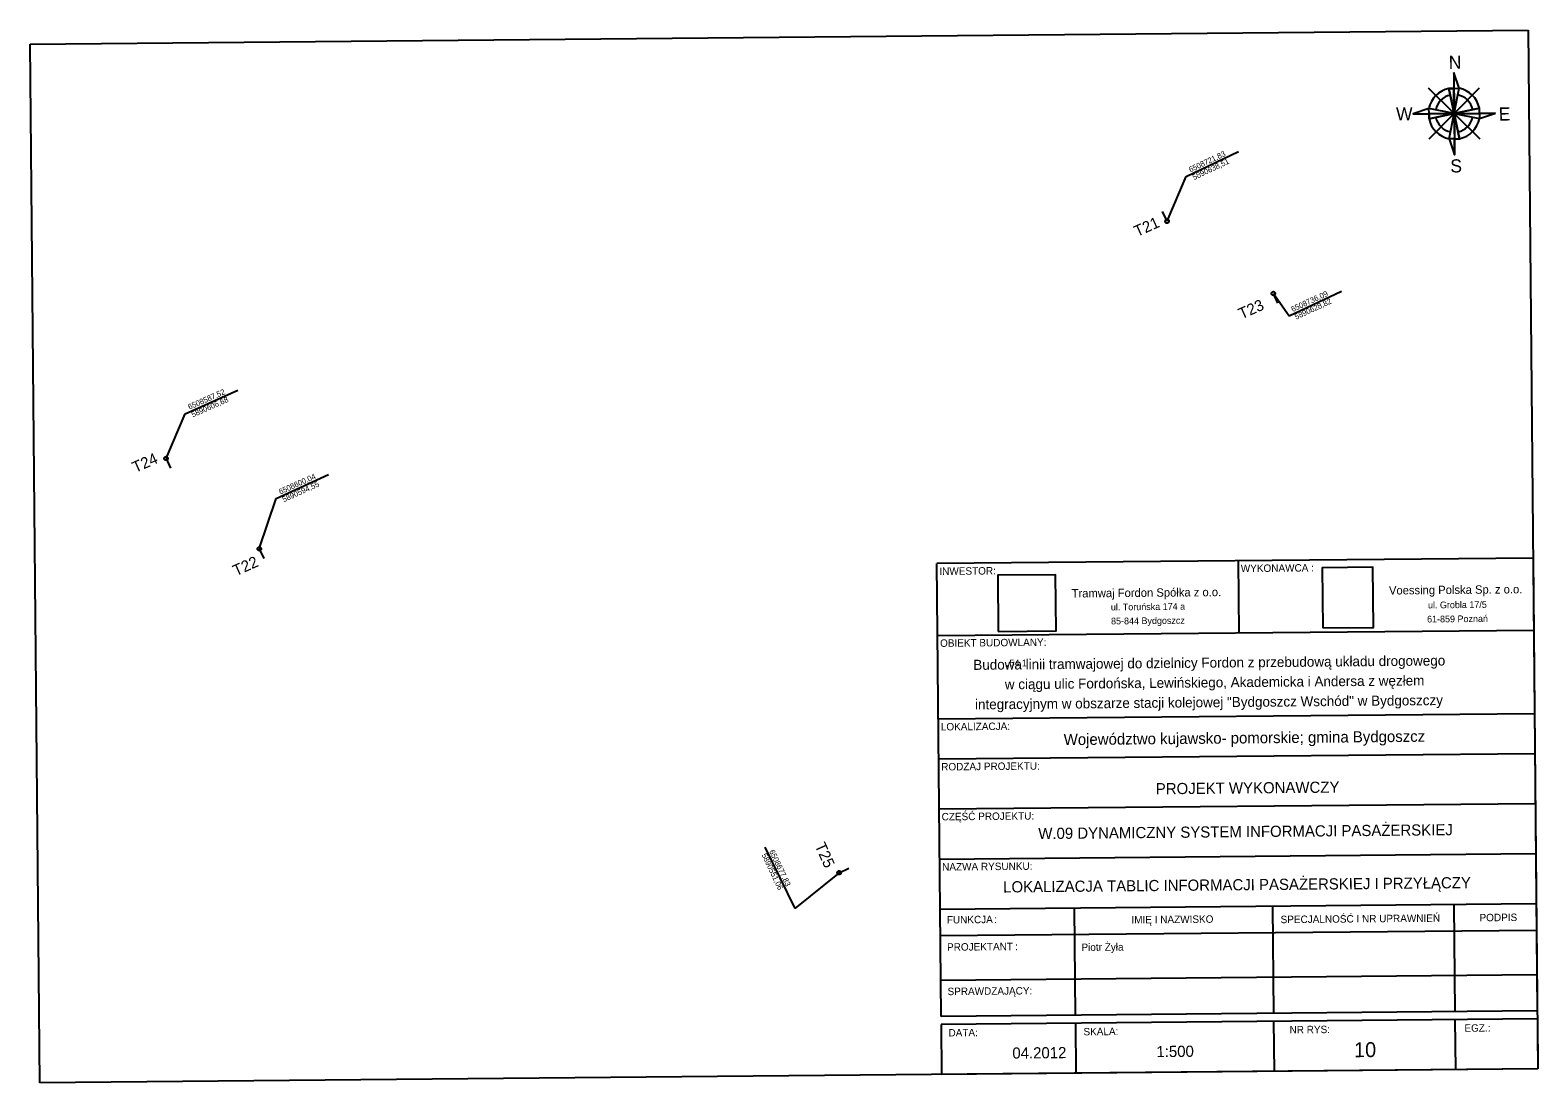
# Model space of a CAD drawing. Extents: x 6505045 to 6511721, y 5887996 to 5893535.
# Drawn here: x 6508569.3 to 6508771.6, y 5890522.8 to 5890664.2 of the extents above; entities that cross this region are included whole.
import ezdxf

# ---------------------------------------------------------------- set-up
doc = ezdxf.new("R2010")
doc.units = 0
for name, color, linetype in [('__legenda', 7, 'Continuous'), ('Default', 7, 'Continuous'), ('P_1 tablica LCD', 7, 'Continuous'), ('P_2 tablice LCD', 7, 'Continuous'), ('P_lokalizacja slupka', 7, 'Continuous'), ('P_opisy', 7, 'Continuous'), ('P_tabela', 7, 'Continuous'), ('P_wsporzedne', 7, 'Continuous'), ('P_znak północy', 7, 'Continuous'), ('SA_Linie-020', 7, 'Continuous'), ('SA_Stempel_Text-020', 7, 'Continuous'), ('SA_Stempel_Text-030', 7, 'Continuous'), ('SA_Stempel_Text-035', 7, 'Continuous'), ('SA_Unterschrift_Text', 7, 'Continuous'), ('WWRPP_801', 7, 'Continuous')]:
    doc.layers.add(name, color=color, linetype=linetype)

msp = doc.modelspace()

# ---------------------------------------------------------------- linework, layer by layer
at = {"layer": '__legenda'}
msp.add_lwpolyline([(6508742.72, 5890583.93), (6508749.52, 5890583.99), (6508749.45, 5890592.06), (6508742.65, 5890592)], close=True, dxfattribs=at)
at = {"layer": 'Default'}
msp.add_lwpolyline([(6508699.19, 5890583.46), (6508706.93, 5890583.53), (6508706.86, 5890591.07), (6508699.12, 5890590.99)], close=True, dxfattribs=at)
at = {"layer": 'P_1 tablica LCD'}
for p, q in [((6508736.7, 5890627.5), (6508736.09, 5890628.82)), ((6508587.52, 5890606.68), (6508588.12, 5890605.36))]:
    msp.add_line(p, q, dxfattribs=at)
at = {"layer": 'P_2 tablice LCD'}
for p, q in [((6508721.83, 5890638.51), (6508721.23, 5890639.83)), ((6508600.04, 5890594.55), (6508600.65, 5890593.24)), ((6508677.83, 5890551.06), (6508679.15, 5890551.67))]:
    msp.add_line(p, q, dxfattribs=at)
at = {"layer": 'P_lokalizacja slupka'}
for centre in [(6508721.83, 5890638.51), (6508736.09, 5890628.82), (6508736.09, 5890628.82), (6508587.52, 5890606.68), (6508600.04, 5890594.55), (6508677.83, 5890551.06)]:
    msp.add_circle(centre, 0.25, dxfattribs=at)
at = {"layer": 'P_tabela'}
for p, q in [((6508569.29, 5890662.3), (6508770.28, 5890664.17)), ((6508569.29, 5890662.3), (6508770.28, 5890664.17)), ((6508770.28, 5890664.17), (6508771.58, 5890524.72)), ((6508770.28, 5890664.17), (6508771.58, 5890524.72)), ((6508570.59, 5890522.85), (6508569.29, 5890662.3)), ((6508570.59, 5890522.85), (6508569.29, 5890662.3)), ((6508771.58, 5890524.72), (6508570.59, 5890522.85)), ((6508771.58, 5890524.72), (6508570.59, 5890522.85))]:
    msp.add_line(p, q, dxfattribs=at)
at = {"layer": 'P_wsporzedne'}
for p, q in [((6508724.4, 5890644.51), (6508731.4, 5890647.89)), ((6508721.83, 5890638.51), (6508724.4, 5890644.51)), ((6508736.09, 5890628.82), (6508738.2, 5890625.83)), ((6508738.2, 5890625.83), (6508745.24, 5890629.13)), ((6508590.08, 5890612.67), (6508597.17, 5890615.85)), ((6508587.52, 5890606.68), (6508590.08, 5890612.67)), ((6508602.28, 5890601.28), (6508609.34, 5890604.52)), ((6508600.04, 5890594.55), (6508602.28, 5890601.28)), ((6508667.88, 5890554.5), (6508671.87, 5890546.25)), ((6508677.83, 5890551.06), (6508671.87, 5890546.25))]:
    msp.add_line(p, q, dxfattribs=at)
at = {"layer": 'P_znak północy'}
for p, q in [((6508760.3, 5890658.49), (6508760.41, 5890647.45)), ((6508760.3, 5890658.49), (6508760.41, 5890647.45)), ((6508760.34, 5890652.97), (6508756.91, 5890656.36)), ((6508760.34, 5890652.97), (6508756.91, 5890656.36)), ((6508759.63, 5890656.35), (6508760.32, 5890656.35)), ((6508760.35, 5890652.98), (6508759.63, 5890656.35)), ((6508759.63, 5890656.35), (6508760.32, 5890656.35)), ((6508760.35, 5890652.98), (6508759.63, 5890656.35)), ((6508760.32, 5890656.35), (6508761.01, 5890656.36)), ((6508760.32, 5890656.35), (6508761.01, 5890656.36)), ((6508760.35, 5890652.98), (6508761.01, 5890656.36)), ((6508760.35, 5890652.98), (6508761.01, 5890656.36)), ((6508760.36, 5890652.99), (6508763.74, 5890656.42)), ((6508760.36, 5890652.99), (6508763.74, 5890656.42)), ((6508754.84, 5890652.92), (6508765.88, 5890653.02)), ((6508754.84, 5890652.92), (6508765.88, 5890653.02)), ((6508760.35, 5890652.98), (6508756.97, 5890653.63)), ((6508760.35, 5890652.98), (6508756.97, 5890653.63)), ((6508760.36, 5890652.99), (6508756.97, 5890649.53)), ((6508760.36, 5890652.99), (6508756.97, 5890649.53)), ((6508756.98, 5890652.25), (6508760.35, 5890652.98)), ((6508756.98, 5890652.25), (6508760.35, 5890652.98)), ((6508756.98, 5890652.94), (6508760.34, 5890652.97)), ((6508760.34, 5890652.97), (6508756.98, 5890652.25)), ((6508756.98, 5890652.94), (6508760.34, 5890652.97)), ((6508760.34, 5890652.97), (6508756.98, 5890652.25)), ((6508756.98, 5890652.25), (6508756.98, 5890652.94)), ((6508756.98, 5890652.25), (6508756.98, 5890652.94)), ((6508759.7, 5890649.59), (6508760.35, 5890652.98)), ((6508759.7, 5890649.59), (6508760.35, 5890652.98)), ((6508760.35, 5890652.98), (6508763.73, 5890653.7)), ((6508760.35, 5890652.98), (6508763.73, 5890653.7)), ((6508760.35, 5890652.98), (6508763.74, 5890652.31)), ((6508760.35, 5890652.98), (6508761.08, 5890649.6)), ((6508760.35, 5890652.98), (6508763.74, 5890652.31)), ((6508760.35, 5890652.98), (6508761.08, 5890649.6)), ((6508760.36, 5890652.99), (6508763.8, 5890649.59)), ((6508760.36, 5890652.99), (6508763.8, 5890649.59))]:
    msp.add_line(p, q, dxfattribs=at)
for points in [[(6508760.3, 5890658.49), (6508760.32, 5890656.35), (6508760.32, 5890656.35), (6508761.01, 5890656.36), (6508760.3, 5890658.49)], [(6508760.3, 5890658.49), (6508760.32, 5890656.35), (6508760.32, 5890656.35), (6508761.01, 5890656.36), (6508760.3, 5890658.49)], [(6508760.36, 5890652.99), (6508760.32, 5890656.35), (6508759.63, 5890656.34), (6508760.35, 5890652.98), (6508760.36, 5890652.99)], [(6508760.36, 5890652.99), (6508760.32, 5890656.35), (6508759.63, 5890656.34), (6508760.35, 5890652.98), (6508760.36, 5890652.99)], [(6508756.98, 5890652.94), (6508756.97, 5890653.63), (6508754.84, 5890652.92), (6508756.98, 5890652.94)], [(6508756.98, 5890652.94), (6508756.97, 5890653.63), (6508754.84, 5890652.92), (6508756.98, 5890652.94)], [(6508760.34, 5890652.97), (6508756.98, 5890652.94), (6508756.98, 5890652.25), (6508760.34, 5890652.97)], [(6508760.34, 5890652.97), (6508756.98, 5890652.94), (6508756.98, 5890652.25), (6508760.34, 5890652.97)], [(6508760.36, 5890652.98), (6508760.36, 5890652.98), (6508760.37, 5890652.97), (6508763.73, 5890653), (6508763.73, 5890653.7), (6508760.36, 5890652.98)], [(6508760.36, 5890652.98), (6508760.36, 5890652.98), (6508760.37, 5890652.97), (6508763.73, 5890653), (6508763.73, 5890653.7), (6508760.36, 5890652.98)], [(6508760.39, 5890649.59), (6508761.08, 5890649.6), (6508760.36, 5890652.96), (6508760.39, 5890649.59)], [(6508760.39, 5890649.59), (6508761.08, 5890649.6), (6508760.36, 5890652.96), (6508760.39, 5890649.59)], [(6508765.88, 5890653.02), (6508763.73, 5890653), (6508763.74, 5890652.31), (6508765.88, 5890653.02)], [(6508765.88, 5890653.02), (6508763.73, 5890653), (6508763.74, 5890652.31), (6508765.88, 5890653.02)], [(6508760.39, 5890649.59), (6508759.7, 5890649.59), (6508760.41, 5890647.45), (6508760.39, 5890649.59)], [(6508760.39, 5890649.59), (6508759.7, 5890649.59), (6508760.41, 5890647.45), (6508760.39, 5890649.59)]]:
    msp.add_lwpolyline(points, dxfattribs=at)
for centre, radius, start, end in [((6508760.35, 5890652.98), 3.45, 102.0474, 168.9738), ((6508760.35, 5890652.98), 3.45, 102.0474, 168.9738), ((6508760.36, 5890652.99), 2.53, 102.1671, 169.2958), ((6508760.36, 5890652.99), 2.53, 102.1671, 169.2958), ((6508760.36, 5890652.99), 2.53, 11.7816, 78.9353), ((6508760.36, 5890652.99), 2.53, 11.7816, 78.9353), ((6508760.36, 5890652.98), 3.45, 12.0554, 79.0163), ((6508760.36, 5890652.98), 3.45, 12.0554, 79.0163), ((6508760.35, 5890652.97), 3.45, 192.0538, 259.0158), ((6508760.35, 5890652.97), 3.45, 192.0538, 259.0158), ((6508760.36, 5890652.99), 2.53, 192.3917, 259.0318), ((6508760.36, 5890652.99), 2.53, 192.3917, 259.0318), ((6508760.36, 5890652.99), 2.53, 282.0081, 348.6723), ((6508760.36, 5890652.99), 2.53, 282.0081, 348.6723), ((6508760.36, 5890652.97), 3.45, 282.0538, 349.0163), ((6508760.36, 5890652.97), 3.45, 282.0538, 349.0163)]:
    msp.add_arc(centre, radius, start, end, dxfattribs=at)
at = {"layer": 'SA_Linie-020'}
for p, q in [((6508770.94, 5890593.3), (6508690.94, 5890592.55)), ((6508691.38, 5890546.13), (6508690.94, 5890592.55)), ((6508731.39, 5890592.93), (6508731.48, 5890583.27)), ((6508770.94, 5890593.3), (6508771.51, 5890532.5)), ((6508691.03, 5890582.89), (6508771.03, 5890583.64)), ((6508771.13, 5890572.41), (6508691.14, 5890571.67)), ((6508771.18, 5890567.04), (6508691.19, 5890566.29)), ((6508771.25, 5890560.32), (6508691.25, 5890559.57)), ((6508771.25, 5890560.32), (6508691.25, 5890559.57)), ((6508771.31, 5890553.6), (6508691.31, 5890552.85)), ((6508771.37, 5890546.88), (6508691.38, 5890546.13)), ((6508691.51, 5890531.76), (6508691.38, 5890546.13)), ((6508709.53, 5890531.93), (6508709.4, 5890546.3)), ((6508735.97, 5890546.55), (6508736.11, 5890532.17)), ((6508760.31, 5890546.77), (6508760.44, 5890532.4)), ((6508771.41, 5890543.32), (6508691.41, 5890542.57)), ((6508771.46, 5890537.36), (6508691.46, 5890536.61)), ((6508771.51, 5890532.5), (6508691.51, 5890531.76)), ((6508771.52, 5890531.44), (6508691.52, 5890530.7)), ((6508691.52, 5890530.7), (6508691.58, 5890523.98)), ((6508709.54, 5890530.87), (6508709.6, 5890524.15)), ((6508736.12, 5890531.11), (6508736.18, 5890524.39)), ((6508760.45, 5890531.34), (6508760.51, 5890524.62)), ((6508771.52, 5890531.44), (6508771.58, 5890524.72)), ((6508771.58, 5890524.72), (6508691.58, 5890523.98))]:
    msp.add_line(p, q, dxfattribs=at)
at = {"layer": 'WWRPP_801'}
msp.add_circle((6508700.35, 5890578.77), 0.045, dxfattribs=at)

# ---------------------------------------------------------------- texts
at = {"layer": 'P_opisy'}
for s, rotation, p in [('T21', 24.2052, (6508717.81, 5890636.39)), ('T23', 24.2052, (6508731.83, 5890625.32)), ('T24', 24.2052, (6508583.41, 5890604.7)), ('T22', 24.2052, (6508596.9, 5890590.84)), ('T25', 294.2052, (6508674.53, 5890554.71))]:
    msp.add_text(s, height=1.501, rotation=rotation, dxfattribs=at).set_placement(p)
at = {"layer": 'P_wsporzedne'}
for s, rotation, p in [('6508721,83', 25.405, (6508724.97, 5890645.05)), ('5890638,51', 25.405, (6508725.46, 5890644.03)), ('6508736,09', 24.7319, (6508738.69, 5890626.32)), ('5890628,82', 24.7319, (6508739.16, 5890625.29)), ('6508587,52', 23.7681, (6508590.67, 5890613.2)), ('5890606,68', 23.7681, (6508591.12, 5890612.17)), ('6508600,04', 24.3024, (6508602.86, 5890601.81)), ('5890594,55', 24.3024, (6508603.32, 5890600.78)), ('6508677,83', 295.405, (6508668.43, 5890553.93)), ('5890551,06', 295.405, (6508667.41, 5890553.45))]:
    msp.add_text(s, height=0.751, rotation=rotation, dxfattribs=at).set_placement(p)
at = {"layer": 'P_znak północy'}
for s, p in [('N', (6508759.63, 5890658.97)), ('N', (6508759.63, 5890658.97)), ('W', (6508752.56, 5890652.05)), ('W', (6508752.56, 5890652.05)), ('E', (6508766.34, 5890652.03)), ('E', (6508766.34, 5890652.03)), ('S', (6508759.84, 5890645.06)), ('S', (6508759.84, 5890645.06))]:
    msp.add_text(s, height=1.76, rotation=0.535, dxfattribs=at).set_placement(p)
at = {"layer": 'SA_Stempel_Text-020'}
for s, p in [('WYKONAWCA :', (6508731.73, 5890591.41)), ('INWESTOR:', (6508691.29, 5890591.03)), ('OBIEKT BUDOWLANY:', (6508691.38, 5890581.38)), ('LOKALIZACJA:', (6508691.48, 5890570.15)), ('RODZAJ PROJEKTU:', (6508691.53, 5890564.78)), ('CZĘŚĆ PROJEKTU:', (6508691.59, 5890558.08)), ('NAZWA RYSUNKU:', (6508691.66, 5890551.34)), ('SPECJALNOŚĆ I NR UPRAWNIEŃ', (6508737.07, 5890544.28)), ('FUNKCJA', (6508692.29, 5890544.24)), (':', (6508698.62, 5890544.3)), ('IMIĘ I NAZWISKO', (6508717.06, 5890544.24)), ('PODPIS', (6508763.76, 5890544.53)), ('PROJEKTANT', (6508692.32, 5890540.58)), (':', (6508701.46, 5890540.66)), ('SPRAWDZAJĄCY:', (6508692.38, 5890534.62)), ('DATA:', (6508692.51, 5890529.07)), ('SKALA:', (6508710.62, 5890529.22)), ('NR RYS:', (6508738.27, 5890529.48)), ('EGZ.:', (6508761.73, 5890529.7))]:
    msp.add_text(s, height=1, rotation=0.535, dxfattribs=at).set_placement(p)
at = {"layer": 'SA_Stempel_Text-030'}
for s, height, p in [('04.2012', 1.5, (6508701.08, 5890526.1)), ('1:500', 1.5, (6508720.41, 5890526.3)), ('10', 2, (6508746.92, 5890526.29))]:
    msp.add_text(s, height=height, rotation=0.535, dxfattribs=at).set_placement(p)
at = {"layer": 'SA_Stempel_Text-035'}
for s, height, p in [('Budowa linii tramwajowej do dzielnicy Fordon z przebudową układu drogowego', 1.35, (6508695.84, 5890578.29)), ('w ciągu ulic Fordońska, Lewińskiego, Akademicka i Andersa z węzłem', 1.35, (6508700.07, 5890575.68)), ('integracyjnym w obszarze stacji kolejowej "Bydgoszcz Wschód" w Bydgoszczy', 1.35, (6508696.07, 5890572.98)), ('Województwo kujawsko- pomorskie; gmina Bydgoszcz', 1.5, (6508707.97, 5890568.19)), ('PROJEKT WYKONAWCZY', 1.5, (6508720.33, 5890561.58)), ('W.09 DYNAMICZNY SYSTEM INFORMACJI PASAŻERSKIEJ', 1.5, (6508704.56, 5890555.57)), ('LOKALIZACJA TABLIC INFORMACJI PASAŻERSKIEJ I PRZYŁĄCZY', 1.5, (6508699.85, 5890548.4))]:
    msp.add_text(s, height=height, rotation=0.535, dxfattribs=at).set_placement(p)
at = {"layer": 'SA_Unterschrift_Text'}
for s, height, p in [('Tramwaj Fordon Spółka z o.o.', 1.125, (6508709.03, 5890588)), ('Voessing Polska Sp. z o.o.', 1.125, (6508751.61, 5890588.4)), ('ul. Toruńska 174 a', 0.9, (6508714.29, 5890586.27)), ('ul. Grobla 17/5', 0.9, (6508756.84, 5890586.54)), ('85-844 Bydgoszcz', 0.9, (6508714.32, 5890584.39)), ('61-859 Poznań', 0.9, (6508756.72, 5890584.65)), ('Piotr Żyła', 1, (6508710.35, 5890540.55))]:
    msp.add_text(s, height=height, rotation=0.535, dxfattribs=at).set_placement(p)
at = {"layer": 'WWRPP_801'}
msp.add_text(' 54.1', height=0.9, dxfattribs=at).set_placement((6508700.35, 5890578.77))

doc.saveas('drawing.dxf')
